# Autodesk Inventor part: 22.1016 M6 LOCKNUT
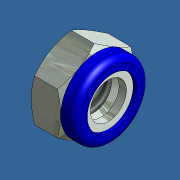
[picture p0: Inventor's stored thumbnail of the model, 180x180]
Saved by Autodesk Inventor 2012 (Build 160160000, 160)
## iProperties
Created: 2008-12
Part Number: 22.1016 M6 LOCKNUT
Document SubType Name: Modellieren
Designer: Oster
Material: Steel
Mass: 2.80936 g
Surface Area: 4.3814 cm^2
Volume: 0.35788 cm^3
Density: 7.85 g/cm^3
Description: Sechskantmutter M06 Selbstsichernd
Übersetzungsnorm: STEP AP214IS
Dateiname: D:\Tpo v2\SharedFS\Outgoing\inafag_xu120222_fi35nr7e9ojhdw2bmfm0916v.stp
Postprozessor: Build: 342, Release: 2008 SP3 - Date: Tue 05/27/2008
Gesendete Einheiten: MILLIMETERS
Unbestimmtheit: 1e-06
Material: Stahl
Beschreibung: Güte:8
Bezeichnung: Sechskantmutter M06 Selbstsichernd
Artikelnr: 211562/0
Lieferantennr: 72401
Zeichnungsnr: leer
MiniTec_ID: 211562/0
Teileart: N
Lieferant: MiniTec
Title: Sechskantmutter M06 Selbstsichernd
Author: Oster
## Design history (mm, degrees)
feature "Basis1"
feature "Gewinde1" dims "d0" = 10, "d1" = 0
node "Volumenkörper1"
node "Volumenkörpern"
node "Oberflächenkörpern"
